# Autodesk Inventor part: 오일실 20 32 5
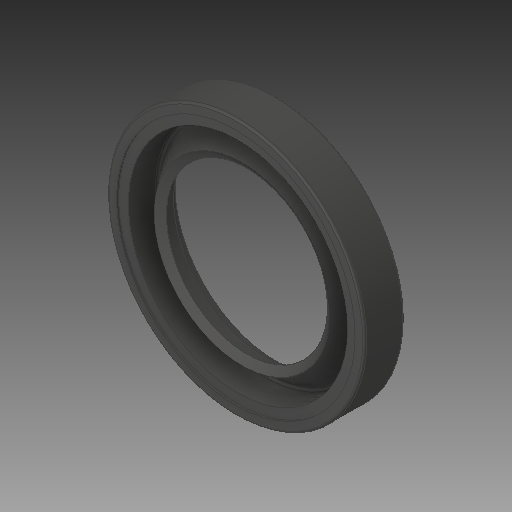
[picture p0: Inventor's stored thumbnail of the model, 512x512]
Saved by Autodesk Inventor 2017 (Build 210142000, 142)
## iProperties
Created: 2024-08
Part Number: 오일실 20 32 5
Material: 일반
Description: 오일 실 - 비스프링, 조립 GA
Document SubType Name: Modeling
Designer: MRC
Density: 1 g/cm^3
Appearance: 기본값
Author: jhkim
Sending System: Autodesk Inventor 2025
Preprocessor: ST-DEVELOPER v20
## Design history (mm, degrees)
feature "Solid1"
node "솔리드1"
